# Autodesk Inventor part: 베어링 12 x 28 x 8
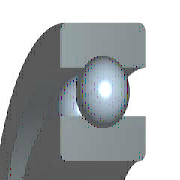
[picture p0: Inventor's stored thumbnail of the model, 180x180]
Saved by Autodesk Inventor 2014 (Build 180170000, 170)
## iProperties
IsCustomPart: 1
Created: 2012-02
Part Number: 베어링 12 x 28 x 8
Material: 강철, 연강
Description: 깊은 그루브 볼 베어링
Document SubType Name: Modeling
Standard: KS B 2023
Designer: mduedu
Standards Organization: KS
Language: ko-KR
Size Designation: 6001 - 12 x 28 x 8
Categories: <MemberInstance><Categories><Category DisplayName="샤프트 부품" InternalName="7f7aeb1f-a693-4053-b835-cee3144e0d98" Mnemonic="SHFT"><Category DisplayName="베어링" Inter
Density: 7.86 g/cm^3
Appearance: 노란색
Mass: 19.7077 g
Surface Area: 31.1809 cm^2
Volume: 2.50734 cm^3
Author: mduedu
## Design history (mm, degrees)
sketch "스케치" dims "d0" = 4.16 (= -0.26 x WD + 0.26 x BD)
  geometry: L1 (1.92, 10)-(6.08, 10); L2 (4, 10)-(4, 7.92); L3 (4, 10)-(4, 12.08); L4 (2.454, 8.608)-(0, 8.608); L5 (0, 6)-(8, 6); L6 (2.454, 11.392)-(0, 11.392); L7 (0, 14)-(8, 14); L8 (8, 6)-(8, 8.608); L9 (5.546, 8.608)-(8, 8.608); L10 (5.546, 11.392)-(8, 11.392); L11 (8, 14)-(8, 11.392); L12 (-1.4, 0)-(8.4, 0) reference; L13 (0, -0.3)-(0, 5.3) reference
  constraints: 22 end point, 4 point on line, 2 collinear, 2 perpendicular, 2 symmetric about line, 1 midpoint, 1 parallel, 14 other
  dimensions: "d9" = 12 diameter of L5 L12 (= WD); "d11" = 28 diameter of L7 L12 (= BD); "d12" = 8 distance between parallel lines of L8 L13 (= KB); "d13" = 17.216 diameter of L9 L12 (= 0.326 x BD + 0.674 x WD)
revolve "본체" stored, may be unused: angle "d6" = 90 deg
revolve "볼" stored, may be unused: angle "d7" = 90 deg
pattern_circular "IDS_ARRAYBALL[SIMPL:T]" dims angle "d3" = 360 deg
body "Solid1"
fillet "모깎기1" dims "d1" = 0.3 (= KRS)
other parameters: "WD" = 12 [user parameter; used in 5 equation terms], "BD" = 28 [user parameter; used in 5 equation terms], "KB" = 8 [user parameter; used in 1 equation term], "KRS" = 0.3 [user parameter; used in 1 equation term], "d4" = 0, "d5" = 0, "d8" = 0, "d14" = 0, "d15" = 0, "BBA" = 0 [user parameter], "BC0" = 2360000 [user parameter], "BC" = 5070000 [user parameter], "BR" = 14 (= 0.5 x BD) [user parameter], "WR" = 6 (= 0.5 x WD) [user parameter]
